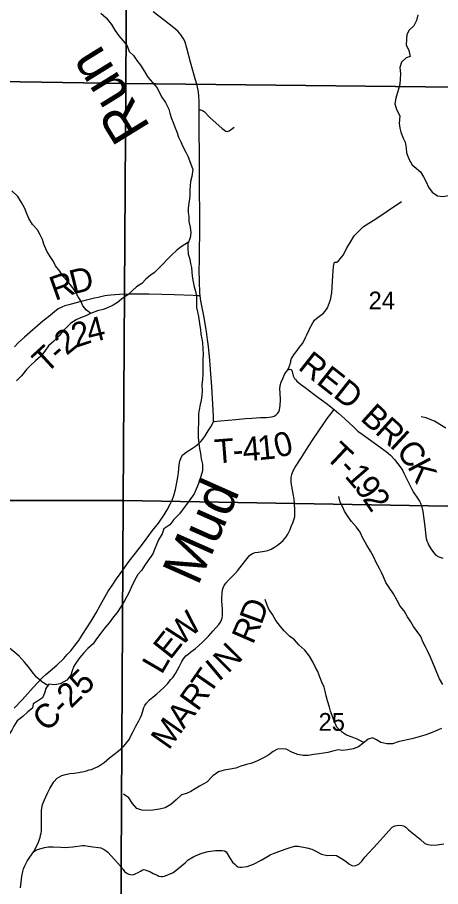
# Model space of a CAD drawing. Extents: x 0 to 191, y 0 to 55.
# Drawn here: x 145.9 to 146.399, y 21.382 to 22.406 of the extents above; entities that cross this region are included whole.
import ezdxf

# ---------------------------------------------------------------- set-up
doc = ezdxf.new("R2010")
doc.units = 0
for name, color, linetype in [('GM_X_Corporation', 7, 'Continuous'), ('GM_X_County_Road', 7, 'Continuous'), ('GM_X_County_Road_Text', 7, 'Continuous'), ('GM_X_Major_Lake', 7, 'Continuous'), ('GM_X_Minor_River', 7, 'Continuous'), ('GM_X_Minor_River_Text', 7, 'Continuous'), ('GM_X_Section_Text', 7, 'Continuous'), ('GM_X_Township_Road', 7, 'Continuous'), ('GM_X_Township_Road_Text', 7, 'Continuous')]:
    doc.layers.add(name, color=color, linetype=linetype)

msp = doc.modelspace()

# ---------------------------------------------------------------- linework, layer by layer
at = {"layer": 'GM_X_Corporation'}
for points in [[(145.5308, 22.8394), (146.0304, 22.8338), (146.0276, 22.3284), (145.5291, 22.3363)], [(146.0304, 22.8338), (146.5294, 22.8286), (146.5261, 22.5754), (146.5224, 22.323), (146.0276, 22.3284)], [(145.5291, 22.3363), (146.0276, 22.3284), (146.0244, 21.8366), (145.525, 21.8368)], [(146.0276, 22.3284), (146.5224, 22.323), (146.52, 22.0665), (146.5198, 21.828), (146.0244, 21.8366)], [(145.525, 21.8368), (146.0244, 21.8366), (146.0215, 21.3343), (145.5183, 21.3384)], [(146.0244, 21.8366), (146.5198, 21.828), (146.519, 21.4945), (146.5178, 21.3308), (146.0215, 21.3343)]]:
    msp.add_lwpolyline(points, close=True, dxfattribs=at)
at = {"layer": 'GM_X_County_Road'}
for points in [[(146.1307, 21.9301), (146.131, 21.9322), (146.131, 21.9358), (146.1302, 21.9505), (146.1288, 21.9708), (146.1274, 21.9912), (146.1265, 22.0022), (146.1251, 22.0184), (146.1239, 22.0267), (146.1226, 22.0359), (146.1193, 22.0544), (146.1157, 22.0722), (146.1149, 22.0782), (146.1147, 22.0815), (146.1141, 22.0951), (146.1139, 22.1086), (146.1142, 22.1191), (146.1141, 22.131), (146.1146, 22.1526), (146.1148, 22.1672), (146.1145, 22.1821), (146.1143, 22.1963), (146.1144, 22.2118), (146.1142, 22.2224), (146.1141, 22.2439), (146.114, 22.2733), (146.114, 22.2973), (146.1138, 22.3029), (146.1138, 22.308), (146.1134, 22.3136), (146.113, 22.3184), (146.1124, 22.3221), (146.1115, 22.3263), (146.1092, 22.334), (146.1037, 22.3534), (146.0993, 22.37), (146.0973, 22.3772), (146.0959, 22.3805), (146.094, 22.3836), (146.0928, 22.3855), (146.0908, 22.3879), (146.0889, 22.3901), (146.0841, 22.3939), (146.0729, 22.4026), (146.0597, 22.413)], [(145.8959, 21.5921), (145.9053, 21.6018), (145.9181, 21.6163), (145.9292, 21.628), (145.9332, 21.6315), (145.9382, 21.6358), (145.9461, 21.6426), (145.9541, 21.6507), (145.9584, 21.6552), (145.9624, 21.6596), (145.9673, 21.6658), (145.9718, 21.6717), (145.9765, 21.6787), (145.9865, 21.6946), (145.9923, 21.7042), (145.9977, 21.7138), (146.0067, 21.7299), (146.0113, 21.7366), (146.0165, 21.7444), (146.0238, 21.7545), (146.0315, 21.7654), (146.0388, 21.7747), (146.0469, 21.7853), (146.059, 21.8013), (146.0658, 21.8099), (146.0726, 21.8199), (146.0761, 21.8258), (146.0797, 21.8323), (146.0819, 21.8372), (146.0841, 21.8428), (146.0859, 21.8498), (146.088, 21.8601), (146.089, 21.8665), (146.0895, 21.8697), (146.0904, 21.8789), (146.091, 21.8833), (146.0925, 21.8874), (146.0943, 21.8903), (146.0966, 21.8923), (146.0996, 21.8946), (146.1047, 21.8976), (146.1096, 21.9009), (146.1117, 21.9024), (146.1138, 21.9042), (146.116, 21.9063), (146.1183, 21.9091), (146.1208, 21.913), (146.1244, 21.9188), (146.1275, 21.9237), (146.1291, 21.9265), (146.1307, 21.9301)]]:
    msp.add_lwpolyline(points, dxfattribs=at)
at = {"layer": 'GM_X_Major_Lake'}
for points in [[(146.3718, 22.4092), (146.3703, 22.4027), (146.3669, 22.3963), (146.3614, 22.3913), (146.3589, 22.386), (146.3584, 22.3801), (146.3582, 22.3741), (146.3612, 22.3672), (146.3629, 22.3604), (146.3582, 22.3585), (146.3527, 22.3537), (146.3506, 22.3471), (146.3514, 22.3399), (146.351, 22.3336), (146.3504, 22.3279), (146.3495, 22.323), (146.3474, 22.3165), (146.3459, 22.311), (146.3448, 22.3046), (146.3468, 22.2978), (146.3506, 22.2904), (146.3497, 22.2814), (146.3507, 22.2759), (146.3516, 22.2712), (146.3546, 22.264), (146.3569, 22.2591), (146.3579, 22.2522), (146.3584, 22.2467), (146.3611, 22.2397), (146.3651, 22.2327)], [(146.3651, 22.2327), (146.375, 22.2243), (146.3783, 22.2183), (146.3818, 22.2123), (146.3842, 22.2063), (146.3888, 22.2003), (146.3948, 22.1958), (146.4014, 22.1951), (146.4078, 22.1964), (146.4148, 22.198), (146.4214, 22.2007), (146.4272, 22.2027), (146.4336, 22.2049), (146.4401, 22.2044), (146.4417, 22.198), (146.4459, 22.1931), (146.4518, 22.1961), (146.4517, 22.2025), (146.4554, 22.2081), (146.4614, 22.2122), (146.4651, 22.2169), (146.4713, 22.2212), (146.4682, 22.2319)]]:
    msp.add_lwpolyline(points, dxfattribs=at)
at = {"layer": 'GM_X_Minor_River'}
for points in [[(145.9981, 22.4112), (146.0044, 22.4058), (146.0105, 22.3978), (146.0145, 22.3912), (146.019, 22.3847), (146.0242, 22.3789), (146.0291, 22.373), (146.0314, 22.3662), (146.0363, 22.3613), (146.0403, 22.3556), (146.0447, 22.3499), (146.0493, 22.3425), (146.0535, 22.3357), (146.0645, 22.3232), (146.0668, 22.3183), (146.0697, 22.3122), (146.0742, 22.306), (146.0782, 22.2982), (146.0794, 22.2935), (146.0813, 22.2872), (146.0832, 22.2825), (146.0857, 22.2762), (146.0874, 22.2713), (146.0895, 22.265), (146.0922, 22.2597), (146.0948, 22.254), (146.0981, 22.2474), (146.1007, 22.2427), (146.1026, 22.2377), (146.1065, 22.2271)], [(146.1065, 22.2271), (146.1052, 22.2189), (146.1035, 22.2128), (146.1033, 22.2079), (146.1028, 22.203), (146.103, 22.1973), (146.1025, 22.1925), (146.1016, 22.1874), (146.1008, 22.1813), (146.1011, 22.1764), (146.1018, 22.1717), (146.1019, 22.1656), (146.1032, 22.159), (146.1042, 22.1523), (146.1033, 22.1464), (146.1005, 22.1394), (146.1006, 22.1341), (146.101, 22.1273), (146.1027, 22.1212), (146.1035, 22.1163), (146.1047, 22.1115), (146.1053, 22.1062), (146.1057, 22.1013), (146.1068, 22.0947), (146.108, 22.0888), (146.1099, 22.0822), (146.1109, 22.0769), (146.1109, 22.0704), (146.1108, 22.0645), (146.112, 22.0594), (146.1131, 22.0539), (146.1139, 22.0483), (146.1147, 22.0429), (146.1153, 22.0382), (146.1159, 22.0327), (146.1169, 22.0274), (146.1177, 22.0227), (146.1183, 22.0157), (146.1187, 22.0094), (146.1181, 22.0035), (146.1182, 21.9973), (146.1184, 21.991), (146.1184, 21.9855), (146.1177, 21.9798), (146.1172, 21.973), (146.1174, 21.9661), (146.1169, 21.9606), (146.1163, 21.955), (146.1151, 21.9498), (146.114, 21.9436), (146.1132, 21.9388), (146.1131, 21.932), (146.1131, 21.9272), (146.1129, 21.9219), (146.1126, 21.917), (146.1126, 21.9109), (146.1136, 21.9043), (146.1144, 21.898), (146.1156, 21.8922), (146.1164, 21.8859), (146.1179, 21.8795), (146.118, 21.8719), (146.1159, 21.8649), (146.1137, 21.8576), (146.1103, 21.8502), (146.1079, 21.8447), (146.103, 21.8377), (146.0989, 21.8319), (146.0949, 21.8268), (146.0906, 21.8209), (146.0842, 21.8144), (146.0792, 21.8083), (146.0724, 21.8033), (146.0703, 21.7973), (146.066, 21.7904), (146.063, 21.7839), (146.0612, 21.779), (146.0591, 21.7739), (146.0533, 21.7655), (146.0499, 21.7607), (146.0458, 21.7544), (146.0415, 21.7495), (146.0375, 21.7426), (146.034, 21.735), (146.0312, 21.7287), (146.0284, 21.7236), (146.0254, 21.7179), (146.0216, 21.7114), (146.0171, 21.7046), (146.013, 21.6998), (146.0077, 21.6926), (146.0028, 21.6865), (145.9978, 21.6802), (145.9929, 21.6739), (145.9888, 21.6678), (145.9825, 21.6623), (145.9778, 21.6571), (145.9731, 21.6516), (145.9694, 21.6463), (145.9662, 21.6413), (145.9641, 21.636)], [(145.986, 22.0573), (145.981, 22.0611), (145.9766, 22.0662), (145.9743, 22.0721), (145.9712, 22.077), (145.9684, 22.0819), (145.9651, 22.0876), (145.9587, 22.0953), (145.9533, 22.1014), (145.9495, 22.107), (145.9444, 22.1136), (145.9421, 22.1186), (145.9382, 22.1244), (145.9344, 22.1307), (145.9306, 22.139), (145.929, 22.1445), (145.9264, 22.15), (145.9231, 22.1558), (145.9174, 22.1622), (145.913, 22.1694), (145.9101, 22.176), (145.9082, 22.1811), (145.9044, 22.1881), (145.9002, 22.1951), (145.8931, 22.2019)], [(146.1012, 22.1412), (146.0926, 22.1358), (146.0877, 22.1319), (146.0809, 22.1256), (146.076, 22.1209), (146.0715, 22.1159), (146.0666, 22.1109), (146.0614, 22.1054), (146.0563, 22.102), (146.051, 22.0978), (146.0461, 22.0928), (146.0401, 22.0886), (146.0352, 22.0842), (146.0303, 22.0796), (146.0225, 22.0741), (146.0177, 22.0704), (146.0124, 22.0672), (146.0058, 22.0641), (146.0007, 22.062), (145.9939, 22.0603), (145.9857, 22.0572), (145.9801, 22.0545), (145.974, 22.0522), (145.9689, 22.0497), (145.9627, 22.046), (145.9529, 22.0361), (145.9486, 22.031), (145.9424, 22.0245), (145.9364, 22.0193), (145.9319, 22.0127), (145.927, 22.0069), (145.921, 22.0016), (145.9151, 21.9961), (145.9102, 21.9913), (145.9044, 21.9837), (145.8986, 21.9779)], [(146.4048, 21.9219), (146.3979, 21.9265), (146.3913, 21.9304), (146.3865, 21.9321), (146.3818, 21.9341), (146.3757, 21.9356)], [(146.4012, 21.6198), (146.3972, 21.6266), (146.3941, 21.6342), (146.3918, 21.64), (146.3893, 21.6453), (146.3866, 21.6521), (146.3836, 21.6589), (146.3807, 21.6642), (146.378, 21.6695), (146.3753, 21.6763), (146.3711, 21.6822), (146.3668, 21.6884), (146.3637, 21.6939), (146.3597, 21.6998), (146.3555, 21.7068), (146.3511, 21.7124), (146.3475, 21.7188), (146.3431, 21.7268), (146.3381, 21.7342), (146.3339, 21.7402), (146.3312, 21.7468), (146.3289, 21.7519), (146.3264, 21.7568), (146.3228, 21.7637), (146.3199, 21.7699), (146.3159, 21.7771), (146.3117, 21.7843), (146.3063, 21.7941), (146.3037, 21.7994), (146.2995, 21.8052), (146.2934, 21.812), (146.2897, 21.8175), (146.2855, 21.8243), (146.2829, 21.8298), (146.2802, 21.8347), (146.2786, 21.8417)], [(146.3081, 21.5513), (146.3001, 21.5556), (146.2943, 21.5579), (146.2876, 21.5603), (146.2829, 21.5631), (146.2764, 21.5694), (146.2728, 21.5777), (146.2707, 21.5832), (146.2689, 21.5883), (146.2676, 21.5932), (146.2653, 21.6006), (146.2637, 21.6065), (146.2624, 21.6119), (146.2612, 21.6169), (146.2585, 21.6227), (146.256, 21.6297), (146.2539, 21.6352), (146.2512, 21.6401), (146.248, 21.6464), (146.2439, 21.6532), (146.2384, 21.6604), (146.2316, 21.6668), (146.2262, 21.6726), (146.2203, 21.6769), (146.2142, 21.683), (146.2097, 21.6883), (146.2043, 21.6954), (146.2003, 21.7022), (146.1959, 21.7085), (146.194, 21.7134), (146.1917, 21.72)], [(145.9356, 21.6188), (145.9285, 21.6229), (145.9222, 21.6287), (145.917, 21.6349), (145.9125, 21.6406), (145.9081, 21.6461), (145.9016, 21.6534), (145.894, 21.6595), (145.8871, 21.6649), (145.8807, 21.67), (145.8682, 21.6778)], [(145.9641, 21.636), (145.9627, 21.6307), (145.9578, 21.6248), (145.9499, 21.6207), (145.9434, 21.6195), (145.9366, 21.6201), (145.9329, 21.6153), (145.9316, 21.6096), (145.9291, 21.6043), (145.9233, 21.6001), (145.918, 21.5972), (145.9173, 21.5919), (145.9118, 21.5877), (145.906, 21.5823), (145.8994, 21.5772), (145.8953, 21.5709), (145.8928, 21.566), (145.8883, 21.5591), (145.884, 21.5524), (145.8789, 21.5463), (145.8699, 21.5404)], [(146.3996, 21.568), (146.3941, 21.5657), (146.3868, 21.5626), (146.3802, 21.5601), (146.3745, 21.5585), (146.3664, 21.5564), (146.3613, 21.5551), (146.3539, 21.5535), (146.3486, 21.5521), (146.3418, 21.55), (146.3352, 21.5498), (146.3282, 21.5514), (146.3232, 21.5546), (146.3185, 21.5569), (146.3132, 21.5555), (146.307, 21.5504), (146.3019, 21.5464), (146.2957, 21.544), (146.2891, 21.5429), (146.2824, 21.5419), (146.2777, 21.5428), (146.2715, 21.5411), (146.2656, 21.5397), (146.2607, 21.5389), (146.2556, 21.5383), (146.2493, 21.5375), (146.2424, 21.5363), (146.2367, 21.5363), (146.2304, 21.5374), (146.2238, 21.5396), (146.2166, 21.5436), (146.2116, 21.5441), (146.2062, 21.5435), (146.2013, 21.5408), (146.196, 21.537), (146.1896, 21.5334), (146.1818, 21.5293), (146.1747, 21.5266), (146.1696, 21.5255), (146.1629, 21.5235), (146.1573, 21.5212), (146.1505, 21.5201), (146.1435, 21.5187), (146.1367, 21.5169), (146.1299, 21.512), (146.1229, 21.5049), (146.1144, 21.4999), (146.1039, 21.4938), (146.099, 21.4915), (146.0931, 21.4896), (146.0867, 21.4838), (146.0805, 21.4783), (146.0737, 21.4743), (146.0671, 21.4729), (146.0592, 21.4719), (146.0516, 21.4715), (146.0461, 21.4716)], [(146.0461, 21.4716), (146.0404, 21.4737), (146.0351, 21.4795), (146.0311, 21.4862), (146.0246, 21.4907)]]:
    msp.add_lwpolyline(points, dxfattribs=at)
at = {"layer": 'GM_X_Township_Road'}
for points in [[(146.114, 22.2973), (146.1158, 22.2972), (146.118, 22.2964), (146.1197, 22.2952), (146.1264, 22.2884), (146.1409, 22.2754), (146.1437, 22.2733), (146.1455, 22.2723), (146.1469, 22.2719), (146.1481, 22.2721), (146.1492, 22.2726), (146.1521, 22.2747), (146.1551, 22.2769)], [(146.2436, 22.038), (146.2438, 22.0384), (146.2479, 22.0462), (146.25, 22.0492), (146.2528, 22.0518), (146.2605, 22.0578), (146.2637, 22.0615), (146.2654, 22.064), (146.2666, 22.0669), (146.2688, 22.0732), (146.2702, 22.0817), (146.2715, 22.1017), (146.2723, 22.1125), (146.2735, 22.1177), (146.2762, 22.1177), (146.2783, 22.1194), (146.2842, 22.1266), (146.2881, 22.1345), (146.2915, 22.1403), (146.2967, 22.1487), (146.3076, 22.1597), (146.3224, 22.1687), (146.3355, 22.178), (146.3525, 22.1891)], [(146.1149, 22.0782), (146.111, 22.0782), (146.1067, 22.0784), (146.0843, 22.0793), (146.0698, 22.0798), (146.0545, 22.08), (146.0427, 22.0802), (146.0311, 22.0802), (146.02, 22.0796), (146.0099, 22.0788), (146.0028, 22.0779), (145.9947, 22.0763), (145.9906, 22.0753), (145.9731, 22.0709), (145.9602, 22.0675), (145.9554, 22.0661), (145.9521, 22.0647), (145.9476, 22.0627), (145.9433, 22.0594), (145.9364, 22.0535), (145.9297, 22.0481), (145.908, 22.0295), (145.9005, 22.0228), (145.896, 22.018)], [(146.2216, 21.9992), (146.2219, 22.0001), (146.2222, 22.0019), (146.2229, 22.0042), (146.2265, 22.0096), (146.2284, 22.0121), (146.2323, 22.0176), (146.2356, 22.0217), (146.2376, 22.0253), (146.2392, 22.0288), (146.241, 22.0322), (146.2436, 22.038)], [(146.1307, 21.9301), (146.1391, 21.9308), (146.1572, 21.9323), (146.1686, 21.9333), (146.1761, 21.9339), (146.1861, 21.9346), (146.1932, 21.9348), (146.1993, 21.9354), (146.2024, 21.9363), (146.2049, 21.9376), (146.2064, 21.9392), (146.2077, 21.9412), (146.2086, 21.9436), (146.2094, 21.9489), (146.2098, 21.9553), (146.2093, 21.9639), (146.2092, 21.9679), (146.2095, 21.9722), (146.2106, 21.9764), (146.2124, 21.9807), (146.2146, 21.9853), (146.2158, 21.9872), (146.2172, 21.9892), (146.2184, 21.9907), (146.22, 21.9944), (146.2212, 21.9977), (146.2216, 21.9992)], [(146.2184, 21.9907), (146.2199, 21.9914), (146.2213, 21.9915), (146.2229, 21.9908), (146.2237, 21.9889), (146.2248, 21.9838), (146.2265, 21.9807), (146.2278, 21.9789), (146.2291, 21.9774), (146.2333, 21.974), (146.239, 21.9699), (146.2493, 21.9623), (146.2555, 21.9576), (146.2638, 21.9514), (146.273, 21.9439), (146.2787, 21.9394), (146.2857, 21.9332), (146.2969, 21.9227), (146.3012, 21.9187), (146.3062, 21.9148), (146.3345, 21.8945), (146.3394, 21.8901), (146.3443, 21.885), (146.3482, 21.8802), (146.3508, 21.8766), (146.3536, 21.8725), (146.3554, 21.8689), (146.3615, 21.8565), (146.3654, 21.8486), (146.3671, 21.846), (146.3713, 21.8397), (146.3739, 21.836), (146.3751, 21.8336), (146.3763, 21.8304), (146.3775, 21.824), (146.3785, 21.818), (146.3801, 21.806), (146.3814, 21.7947), (146.3818, 21.792), (146.3823, 21.7893), (146.3834, 21.7867), (146.3844, 21.7847), (146.3869, 21.7805), (146.3903, 21.7756), (146.3932, 21.7725), (146.3964, 21.7705), (146.4011, 21.7687)], [(145.903, 21.3801), (145.9049, 21.394), (145.906, 21.3993), (145.9069, 21.4025), (145.9082, 21.406), (145.9112, 21.4117), (145.9142, 21.4164), (145.9189, 21.423), (145.9235, 21.4319), (145.9245, 21.4341), (145.9254, 21.4364), (145.9263, 21.4396), (145.9269, 21.4421), (145.9274, 21.4445), (145.9278, 21.4469), (145.928, 21.4496), (145.9281, 21.4521), (145.9281, 21.4617), (145.9281, 21.4663), (145.928, 21.4715), (145.9283, 21.4739), (145.9293, 21.4783), (145.9313, 21.4839), (145.9329, 21.4875), (145.9355, 21.4927), (145.9377, 21.4973), (145.9425, 21.5051), (145.9465, 21.5093), (145.949, 21.511), (145.9519, 21.5125), (145.9563, 21.5137), (145.9614, 21.5148), (145.9666, 21.5155), (145.9715, 21.5162), (145.9777, 21.5175), (145.981, 21.5182), (145.9842, 21.5191), (145.9869, 21.5198), (145.9894, 21.5207), (145.9947, 21.5231), (145.9985, 21.5256), (146.0018, 21.5281), (146.0083, 21.5333), (146.0182, 21.5414), (146.0216, 21.5441), (146.0249, 21.5471), (146.0272, 21.5497), (146.0299, 21.5529), (146.0316, 21.5555), (146.033, 21.5585), (146.036, 21.5644), (146.0393, 21.5707), (146.0428, 21.5772), (146.0447, 21.5808), (146.0462, 21.5845), (146.0485, 21.5928), (146.0499, 21.5953), (146.0518, 21.5978), (146.0555, 21.6016), (146.0592, 21.605), (146.0638, 21.6088), (146.0677, 21.6121), (146.0723, 21.6162), (146.0765, 21.6208), (146.0805, 21.6256), (146.0831, 21.6286), (146.0859, 21.6327), (146.0884, 21.6371), (146.0902, 21.6407), (146.0936, 21.6469), (146.0956, 21.6503), (146.098, 21.6535), (146.1008, 21.6558), (146.104, 21.6583), (146.1094, 21.6625), (146.118, 21.6698), (146.1248, 21.6769), (146.1303, 21.6831), (146.1369, 21.6905), (146.1391, 21.6935), (146.1404, 21.6963), (146.141, 21.6984), (146.1413, 21.701), (146.1416, 21.7051), (146.1414, 21.7087), (146.1408, 21.7184), (146.1408, 21.7223), (146.141, 21.727), (146.1415, 21.7313), (146.1422, 21.734), (146.1434, 21.7365), (146.1453, 21.7394), (146.1485, 21.7429), (146.1524, 21.7467), (146.1559, 21.7504), (146.159, 21.7538), (146.1619, 21.7574), (146.1688, 21.7664), (146.1737, 21.7723), (146.1769, 21.7744), (146.1798, 21.7755), (146.1836, 21.776), (146.1911, 21.777), (146.1947, 21.7778), (146.1988, 21.7795), (146.2028, 21.7816), (146.2062, 21.7841), (146.2099, 21.7868), (146.2131, 21.7897), (146.2151, 21.7921), (146.2164, 21.7939), (146.2183, 21.7971), (146.2211, 21.8026), (146.2226, 21.806), (146.2245, 21.8103), (146.2261, 21.8151), (146.2266, 21.8178), (146.2269, 21.8211), (146.2269, 21.8252), (146.2264, 21.8337), (146.2261, 21.8378), (146.2251, 21.8428), (146.2226, 21.8582), (146.2224, 21.8607), (146.2223, 21.8636), (146.2227, 21.8659), (146.2232, 21.8676), (146.2243, 21.8708), (146.2271, 21.876), (146.2345, 21.8874), (146.2426, 21.8999), (146.2493, 21.9101), (146.2603, 21.9264), (146.265, 21.9333), (146.2679, 21.9374), (146.273, 21.9439)], [(145.9189, 21.423), (145.921, 21.4243), (145.9233, 21.4252), (145.9276, 21.4267), (145.9316, 21.4277), (145.9339, 21.4281), (145.9364, 21.4283), (145.9416, 21.4283), (145.9508, 21.428), (145.956, 21.4278), (145.9598, 21.428), (145.965, 21.4285), (145.9763, 21.4299), (145.9788, 21.4301), (145.9811, 21.4298), (145.9886, 21.4285), (145.9952, 21.4277), (145.9978, 21.4272), (145.9997, 21.4266), (146.002, 21.4255), (146.0042, 21.4239), (146.006, 21.4222), (146.0141, 21.4136), (146.0176, 21.4097), (146.0208, 21.4059), (146.0226, 21.4034), (146.0241, 21.4018), (146.026, 21.3996), (146.0274, 21.3984), (146.0293, 21.3972), (146.031, 21.3964), (146.033, 21.3958), (146.0357, 21.3956), (146.0385, 21.3965), (146.0419, 21.3983), (146.0447, 21.3999), (146.0467, 21.4009), (146.0486, 21.4017), (146.0503, 21.4013), (146.0522, 21.4005), (146.0556, 21.3993), (146.0595, 21.3972), (146.0642, 21.395), (146.0664, 21.3941), (146.0691, 21.3935), (146.0708, 21.3935), (146.073, 21.394), (146.0776, 21.3957), (146.0826, 21.3979), (146.0845, 21.3989), (146.0972, 21.4097), (146.1011, 21.4132), (146.1077, 21.4171), (146.1171, 21.4209), (146.1246, 21.4231), (146.1332, 21.4241), (146.1383, 21.4243), (146.1412, 21.4242), (146.1438, 21.4239), (146.1457, 21.4225), (146.1471, 21.4207), (146.1498, 21.4158), (146.1532, 21.4103), (146.1559, 21.408), (146.1576, 21.4066), (146.1596, 21.4051), (146.1619, 21.4044), (146.164, 21.4046), (146.1704, 21.4052), (146.178, 21.4081), (146.1872, 21.4126), (146.1944, 21.4171), (146.1978, 21.419), (146.2017, 21.4208), (146.2078, 21.4229), (146.2152, 21.4256), (146.2226, 21.428), (146.2269, 21.4292), (146.2308, 21.4292), (146.241, 21.4272), (146.2469, 21.4256), (146.2515, 21.4235), (146.2582, 21.4199), (146.265, 21.4184), (146.2697, 21.4188), (146.2757, 21.4184), (146.2819, 21.4148), (146.2871, 21.4113), (146.2906, 21.4084), (146.2947, 21.4059), (146.2987, 21.4064), (146.3024, 21.4082), (146.3058, 21.4116), (146.3094, 21.4162), (146.3238, 21.432), (146.3417, 21.4518), (146.3445, 21.4532), (146.3492, 21.4541), (146.3528, 21.4537), (146.3553, 21.4531), (146.3578, 21.4517), (146.3609, 21.4487), (146.3667, 21.4439), (146.3747, 21.4377), (146.3799, 21.4323), (146.3835, 21.4312), (146.3881, 21.4304), (146.3945, 21.4308), (146.4025, 21.432)]]:
    msp.add_lwpolyline(points, dxfattribs=at)

# ---------------------------------------------------------------- texts
at = {"layer": 'GM_X_County_Road_Text'}
msp.add_text('C-25', height=0.02841, rotation=44.3139, dxfattribs=at).set_placement((145.9341, 21.5629))
at = {"layer": 'GM_X_Minor_River_Text'}
for s, rotation, p in [('Run', 121.6893, (146.0572, 22.2769)), ('Mud', 66.0668, (146.1123, 21.7351))]:
    msp.add_text(s, height=0.04734, rotation=rotation, dxfattribs=at).set_placement(p)
at = {"layer": 'GM_X_Section_Text'}
for s, p in [('24', (146.3137, 22.0621)), ('25', (146.2547, 21.5653))]:
    msp.add_text(s, height=0.02093, rotation=0, dxfattribs=at).set_placement(p)
at = {"layer": 'GM_X_Township_Road_Text'}
for s, height, rotation, p in [('R', 0.0284, 19.5199, (145.9438, 22.072)), ('D', 0.0284, 14.1723, (145.9651, 22.0796)), ('4', 0.0284, 14.1524, (145.9848, 22.0222)), ('2', 0.0284, 18.2556, (145.9687, 22.0168)), ('2', 0.0284, 39.2132, (145.9575, 22.0071)), ('T', 0.0284, 42.5507, (145.9334, 21.9853)), ('-', 0.0284, 41.2329, (145.949, 21.9996)), ('RED', 0.02841, 321.7667, (146.2293, 21.9924)), ('B', 0.0284, 318.0151, (146.3028, 21.9323)), ('R', 0.0284, 317.9571, (146.3201, 21.9167)), ('I', 0.0284, 317.2858, (146.3374, 21.9011)), ('T', 0.0284, 4.4444, (146.1331, 21.8803)), ('4', 0.0284, 4.7069, (146.1661, 21.8828)), ('1', 0.0284, 5.6169, (146.184, 21.8843)), ('0', 0.0284, 14.3785, (146.2061, 21.8868)), ('T', 0.0284, 316.8246, (146.2613, 21.8875)), ('C', 0.0284, 308.6062, (146.3452, 21.8941)), ('-', 0.0284, 4.4984, (146.1544, 21.8819)), ('-', 0.0284, 314.575, (146.2766, 21.8732)), ('K', 0.0284, 297.7479, (146.359, 21.877)), ('1', 0.0284, 310.8457, (146.2845, 21.8652)), ('9', 0.0284, 306.9813, (146.2956, 21.8524)), ('2', 0.0284, 304.5806, (146.3059, 21.8386)), ('D', 0.0284, 69.9737, (146.1873, 21.6892)), ('W', 0.0284, 42.2934, (146.0921, 21.6639)), ('R', 0.0284, 66.5702, (146.1773, 21.6661)), ('E', 0.0284, 51.63, (146.0798, 21.6481)), ('N', 0.0284, 45.1979, (146.1478, 21.632)), ('L', 0.0284, 59.8043, (146.0697, 21.6307)), ('I', 0.0284, 39.9815, (146.1368, 21.6226)), ('T', 0.0284, 55.3891, (146.126, 21.6066)), ('R', 0.0284, 54.3135, (146.1121, 21.5872)), ('A', 0.0284, 51.5023, (146.0956, 21.5664)), ('M', 0.0284, 54.7967, (146.0781, 21.5415))]:
    msp.add_text(s, height=height, rotation=rotation, dxfattribs=at).set_placement(p)

doc.saveas('drawing.dxf')
